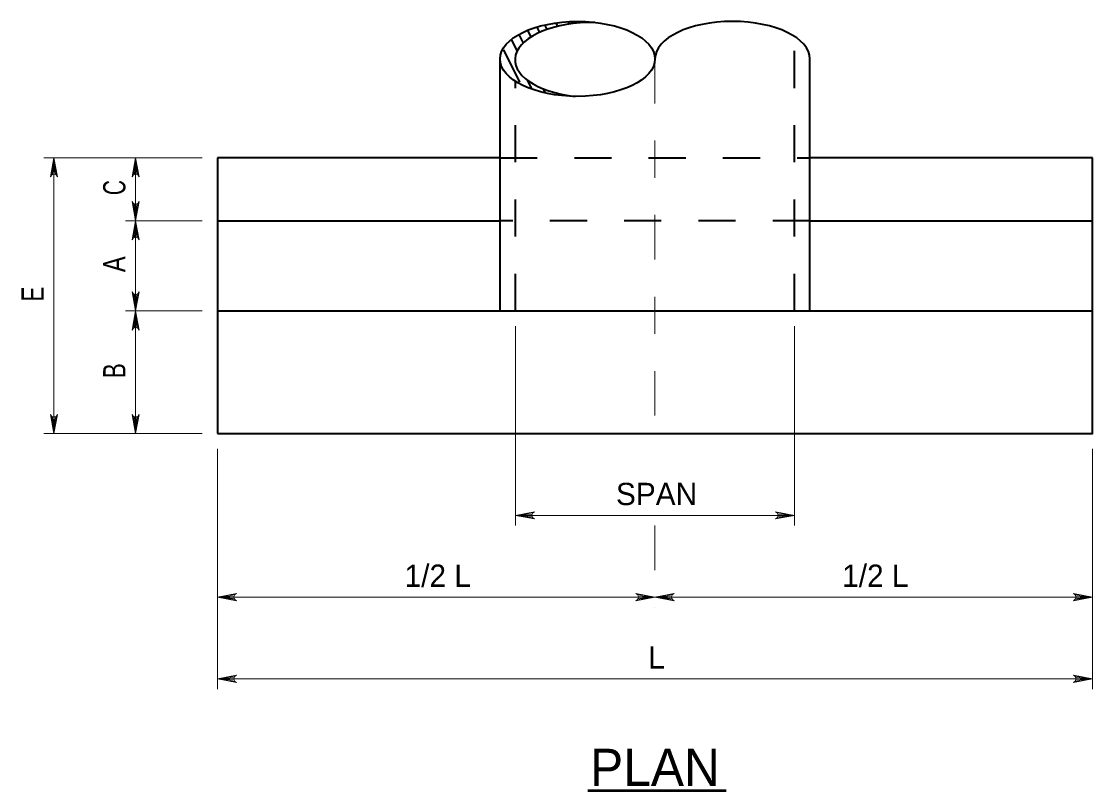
# Model space of a CAD drawing. Extents: x 394.95 to 401.96, y -76.51 to -66.78.
# Drawn here: x 395.214 to 398.097, y -68.852 to -66.782 of the extents above; entities that cross this region are included whole.
import ezdxf
from ezdxf.enums import TextEntityAlignment as Align

# ---------------------------------------------------------------- set-up
doc = ezdxf.new("R2010")
doc.units = 0
doc.header["$LTSCALE"] = 0.024
for name, pattern in [('DOT_DASHED', [7.7, 5, -1.2, 0.3, -1.2]), ('LONG_DASHED', [7.5, 6, -1.5]), ('SHORT_DASHED', [2.7, 1.5, -1.2])]:
    doc.linetypes.add(name, pattern=pattern)
for name, color, linetype, lineweight in [('1', 7, 'LONG_DASHED', 35), ('10', 7, 'Continuous', 13), ('13', 7, 'Continuous', 25)]:
    doc.layers.add(name, color=color, linetype=linetype, lineweight=lineweight)
doc.layers.add('12', color=7, linetype='Continuous')

msp = doc.modelspace()

# ---------------------------------------------------------------- linework, layer by layer
at = {"layer": '1', "linetype": 'Continuous'}
for p, q in [((396.57601, -66.8058), (396.58517, -66.82414)), ((396.6011, -66.79699), (396.60845, -66.81168)), ((396.62217, -66.79148), (396.62829, -66.80374)), ((396.65204, -66.786), (396.6567, -66.79533)), ((396.68556, -66.78267), (396.68875, -66.78903)), ((396.71627, -66.78196), (396.71814, -66.78569)), ((396.53244, -66.83048), (396.54815, -66.86193)), ((396.55262, -66.81702), (396.56429, -66.84037)), ((396.51124, -66.8585), (396.55472, -66.94553)), ((396.50223, -67.56109), (396.50223, -66.88276)), ((397.3364, -67.56109), (397.3364, -66.88276)), ((396.57569, -66.93985), (396.58786, -66.96422)), ((396.61769, -66.96279), (396.62345, -66.97432)), ((396.65409, -66.97454), (396.65691, -66.98017)), ((395.7414, -67.14859), (395.7414, -67.89109)), ((396.50223, -67.14859), (395.7414, -67.14859)), ((398.09723, -67.14859), (397.3364, -67.14859)), ((395.7414, -67.31818), (396.50223, -67.31818)), ((397.3364, -67.31818), (398.09723, -67.31818)), ((395.7414, -67.56109), (398.09723, -67.56109))]:
    msp.add_line(p, q, dxfattribs=at)
at = {"layer": '1', "linetype": 'SHORT_DASHED'}
for p, q in [((397.29515, -67.56109), (397.29515, -66.82256)), ((396.54348, -67.56109), (396.54348, -66.94296)), ((396.50223, -67.14859), (397.3364, -67.14859)), ((397.3364, -67.31818), (396.50223, -67.31818))]:
    msp.add_line(p, q, dxfattribs=at)
at = {"layer": '1', "linetype": 'Continuous'}
msp.add_lwpolyline([(395.7414, -67.89109), (398.09723, -67.89109), (398.09723, -67.14859)], dxfattribs=at)
msp.add_ellipse((396.71077, -66.88276), major_axis=(-0.20854, 0), ratio=0.483516, dxfattribs=at)
for centre, start_param, end_param in [((396.75103, -66.88526), 4.6819539, 7.6283934), ((397.12785, -66.88276), 3.1415927, 6.2831853)]:
    msp.add_ellipse(centre, major_axis=(-0.20854, 0), ratio=0.483516, start_param=start_param, end_param=end_param, dxfattribs=at)
at = {"layer": '10', "linetype": 'DOT_DASHED'}
for p, q in [((396.91931, -66.88276), (396.91931, -67.93377)), ((396.91931, -68.13859), (396.91931, -68.35859))]:
    msp.add_line(p, q, dxfattribs=at)
at = {"layer": '10'}
for p, q in [((395.70015, -67.14859), (395.2739, -67.14859)), ((395.3014, -67.14859), (395.3014, -67.89109)), ((395.70015, -67.31818), (395.4939, -67.31818)), ((395.70015, -67.56109), (395.4939, -67.56109)), ((395.5214, -67.56109), (395.5214, -67.89109)), ((396.54348, -67.60234), (396.54348, -68.13859)), ((397.29515, -67.60234), (397.29515, -68.13859)), ((395.70015, -67.89109), (395.2739, -67.89109)), ((395.7414, -67.93234), (395.7414, -68.57859)), ((398.09723, -67.93234), (398.09723, -68.57859)), ((396.54348, -68.11109), (397.29515, -68.11109)), ((395.7414, -68.55109), (398.09723, -68.55109))]:
    msp.add_line(p, q, dxfattribs=at)
for points in [[(395.3014, -67.14859), (395.311, -67.19985), (395.30827, -67.19591), (395.30483, -67.19386), (395.3014, -67.19328), (395.29796, -67.19386), (395.29452, -67.19591), (395.29178, -67.19985), (395.3014, -67.14859), (395.29452, -67.19591), (395.29796, -67.19386), (395.3014, -67.14859), (395.3014, -67.19328), (395.30483, -67.19386), (395.3014, -67.14859), (395.30827, -67.19591)], [(395.5214, -67.14859), (395.531, -67.19985), (395.52827, -67.19591), (395.52483, -67.19386), (395.5214, -67.19328), (395.51796, -67.19386), (395.51452, -67.19591), (395.51178, -67.19985), (395.5214, -67.14859), (395.51452, -67.19591), (395.51796, -67.19386), (395.5214, -67.14859), (395.5214, -67.19328), (395.52483, -67.19386), (395.5214, -67.14859), (395.52827, -67.19591)], [(395.5214, -67.14859), (395.5214, -67.31818), (395.5214, -67.56109)], [(395.5214, -67.31818), (395.531, -67.26692), (395.52827, -67.27086), (395.52483, -67.2729), (395.5214, -67.27349), (395.51796, -67.2729), (395.51452, -67.27086), (395.51178, -67.26692), (395.5214, -67.31818), (395.51452, -67.27086), (395.51796, -67.2729), (395.5214, -67.31818), (395.5214, -67.27349), (395.52483, -67.2729), (395.5214, -67.31818), (395.52827, -67.27086)], [(395.5214, -67.31818), (395.531, -67.36944), (395.52827, -67.36549), (395.52483, -67.36345), (395.5214, -67.36286), (395.51796, -67.36345), (395.51452, -67.36549), (395.51178, -67.36944), (395.5214, -67.31818), (395.51452, -67.36549), (395.51796, -67.36345), (395.5214, -67.31818), (395.5214, -67.36286), (395.52483, -67.36345), (395.5214, -67.31818), (395.52827, -67.36549)], [(395.5214, -67.56109), (395.531, -67.50983), (395.52827, -67.51378), (395.52483, -67.51581), (395.5214, -67.51641), (395.51796, -67.51581), (395.51452, -67.51378), (395.51178, -67.50983), (395.5214, -67.56109), (395.51452, -67.51378), (395.51796, -67.51581), (395.5214, -67.56109), (395.5214, -67.51641), (395.52483, -67.51581), (395.5214, -67.56109), (395.52827, -67.51378)], [(395.5214, -67.56109), (395.531, -67.61235), (395.52827, -67.60841), (395.52483, -67.60636), (395.5214, -67.60578), (395.51796, -67.60636), (395.51452, -67.60841), (395.51178, -67.61235), (395.5214, -67.56109), (395.51452, -67.60841), (395.51796, -67.60636), (395.5214, -67.56109), (395.5214, -67.60578), (395.52483, -67.60636), (395.5214, -67.56109), (395.52827, -67.60841)], [(395.3014, -67.89109), (395.29178, -67.83983), (395.29452, -67.84378), (395.29796, -67.84581), (395.3014, -67.84641), (395.30483, -67.84581), (395.30827, -67.84378), (395.311, -67.83983), (395.3014, -67.89109), (395.30827, -67.84378), (395.30483, -67.84581), (395.3014, -67.89109), (395.3014, -67.84641), (395.29796, -67.84581), (395.3014, -67.89109), (395.29452, -67.84378)], [(395.5214, -67.89109), (395.51178, -67.83983), (395.51452, -67.84378), (395.51796, -67.84581), (395.5214, -67.84641), (395.52483, -67.84581), (395.52827, -67.84378), (395.531, -67.83983), (395.5214, -67.89109), (395.52827, -67.84378), (395.52483, -67.84581), (395.5214, -67.89109), (395.5214, -67.84641), (395.51796, -67.84581), (395.5214, -67.89109), (395.51452, -67.84378)], [(396.54348, -68.11109), (396.59474, -68.10148), (396.59079, -68.10422), (396.58875, -68.10766), (396.58817, -68.11109), (396.58875, -68.11453), (396.59079, -68.11797), (396.59474, -68.12071), (396.54348, -68.11109), (396.59079, -68.11797), (396.58875, -68.11453), (396.54348, -68.11109), (396.58817, -68.11109), (396.58875, -68.10766), (396.54348, -68.11109), (396.59079, -68.10422)], [(397.29515, -68.11109), (397.24388, -68.12071), (397.24782, -68.11797), (397.24986, -68.11453), (397.25046, -68.11109), (397.24986, -68.10766), (397.24782, -68.10422), (397.24388, -68.10148), (397.29515, -68.11109), (397.24782, -68.10422), (397.24986, -68.10766), (397.29515, -68.11109), (397.25046, -68.11109), (397.24986, -68.11453), (397.29515, -68.11109), (397.24782, -68.11797)], [(395.7414, -68.33109), (395.79266, -68.32148), (395.78871, -68.32422), (395.78667, -68.32766), (395.78608, -68.33109), (395.78667, -68.33453), (395.78871, -68.33797), (395.79266, -68.34071), (395.7414, -68.33109), (395.78871, -68.33797), (395.78667, -68.33453), (395.7414, -68.33109), (395.78608, -68.33109), (395.78667, -68.32766), (395.7414, -68.33109), (395.78871, -68.32422)], [(395.7414, -68.33109), (396.91931, -68.33109), (398.09723, -68.33109)], [(396.91931, -68.33109), (396.86804, -68.34071), (396.87199, -68.33797), (396.87403, -68.33453), (396.87462, -68.33109), (396.87403, -68.32766), (396.87199, -68.32422), (396.86804, -68.32148), (396.91931, -68.33109), (396.87199, -68.32422), (396.87403, -68.32766), (396.91931, -68.33109), (396.87462, -68.33109), (396.87403, -68.33453), (396.91931, -68.33109), (396.87199, -68.33797)], [(396.91931, -68.33109), (396.97057, -68.34071), (396.96662, -68.33797), (396.96458, -68.33453), (396.964, -68.33109), (396.96458, -68.32766), (396.96662, -68.32422), (396.97057, -68.32148), (396.91931, -68.33109), (396.96662, -68.32422), (396.96458, -68.32766), (396.91931, -68.33109), (396.964, -68.33109), (396.96458, -68.33453), (396.91931, -68.33109), (396.96662, -68.33797)], [(398.09723, -68.33109), (398.04596, -68.34071), (398.04991, -68.33797), (398.05195, -68.33453), (398.05254, -68.33109), (398.05195, -68.32766), (398.04991, -68.32422), (398.04596, -68.32148), (398.09723, -68.33109), (398.04991, -68.32422), (398.05195, -68.32766), (398.09723, -68.33109), (398.05254, -68.33109), (398.05195, -68.33453), (398.09723, -68.33109), (398.04991, -68.33797)], [(395.7414, -68.55109), (395.79266, -68.54148), (395.78871, -68.54422), (395.78667, -68.54766), (395.78608, -68.55109), (395.78667, -68.55453), (395.78871, -68.55797), (395.79266, -68.56071), (395.7414, -68.55109), (395.78871, -68.55797), (395.78667, -68.55453), (395.7414, -68.55109), (395.78608, -68.55109), (395.78667, -68.54766), (395.7414, -68.55109), (395.78871, -68.54422)], [(398.09723, -68.55109), (398.04596, -68.56071), (398.04991, -68.55797), (398.05195, -68.55453), (398.05254, -68.55109), (398.05195, -68.54766), (398.04991, -68.54422), (398.04596, -68.54148), (398.09723, -68.55109), (398.04991, -68.54422), (398.05195, -68.54766), (398.09723, -68.55109), (398.05254, -68.55109), (398.05195, -68.55453), (398.09723, -68.55109), (398.04991, -68.55797)]]:
    msp.add_lwpolyline(points, dxfattribs=at)
at = {"layer": '13', "lineweight": 53}
msp.add_line((396.73836, -68.85173), (397.11059, -68.85173), dxfattribs=at)

# ---------------------------------------------------------------- texts
at = {"layer": '12'}
for s, width, p in [('C', 0.7, (395.4939, -67.22915)), ('A', 0.8, (395.4939, -67.4354)), ('E', 0.75, (395.2739, -67.51562)), ('B', 0.75, (395.4939, -67.72186))]:
    msp.add_text(s, height=0.06, rotation=90, dxfattribs=dict(at, width=width)).set_placement(p, align=Align.CENTER)
for s, height, p in [('SPAN', 0.06, (396.92353, -68.08358)), ('1/2 L', 0.06, (396.33456, -68.30358)), ('1/2 L', 0.06, (397.51248, -68.30358)), ('PLAN', 0.1, (396.91931, -68.83922))]:
    msp.add_text(s, height=height, dxfattribs=at).set_placement(p, align=Align.CENTER)
at = {"layer": '13'}
msp.add_text('L', height=0.06, dxfattribs=at).set_placement((396.92351, -68.52358), align=Align.CENTER)

doc.saveas('drawing.dxf')
